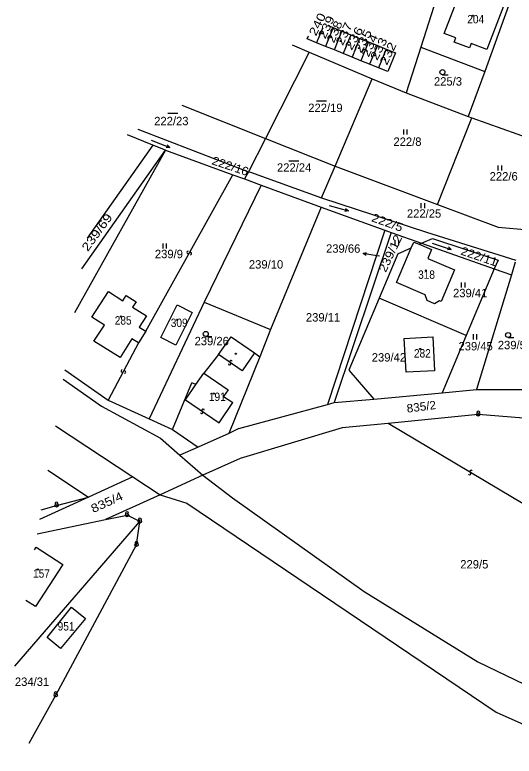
# Model space of a CAD drawing. Extents: x -680102 to -677253, y -1007548 to -1006096.
# Drawn here: x -680102.2 to -679953.4, y -1007313.8 to -1007092.8 of the extents above; entities that cross this region are included whole.
import ezdxf
from ezdxf.enums import TextEntityAlignment as Align

# ---------------------------------------------------------------- set-up
doc = ezdxf.new("R2010")
doc.units = 0
for name, color, linetype, lineweight in [('1', 7, 'Continuous', 25), ('16', 7, 'Continuous', 25), ('24', 7, 'Continuous', 25), ('25', 7, 'Continuous', 25), ('4', 7, 'Continuous', 25)]:
    doc.layers.add(name, color=color, linetype=linetype, lineweight=lineweight)
doc.layers.add('18', color=7, linetype='Continuous')
doc.layers.add('19', color=7, linetype='Continuous')

msp = doc.modelspace()

# ---------------------------------------------------------------- linework, layer by layer
at = {"layer": '1'}
for p, q in [((-679954.1, -1007087.39), (-679962.13, -1007109.73)), ((-680010.48, -1007096.84), (-680012.22, -1007101.17)), ((-680007.33, -1007096.64), (-680009.58, -1007102.24)), ((-680015, -1007100.04), (-680014.62, -1007099.1)), ((-680006.94, -1007103.31), (-680004.69, -1007097.71)), ((-680002.05, -1007098.79), (-680004.29, -1007104.38)), ((-679999.4, -1007099.86), (-680001.65, -1007105.45)), ((-679996.76, -1007100.93), (-679999.01, -1007106.52)), ((-680014.47, -1007103.93), (-680027.49, -1007129.66)), ((-679994.12, -1007102), (-679996.46, -1007107.56)), ((-679991.48, -1007103.07), (-679993.81, -1007108.63)), ((-679995.66, -1007111.97), (-679985.54, -1007116.09)), ((-680052.38, -1007119.74), (-680027.49, -1007129.66)), ((-679976.19, -1007149.36), (-679965.95, -1007123.53)), ((-679967.03, -1007123.14), (-679965.95, -1007123.53)), ((-679965.95, -1007123.53), (-679939.69, -1007132.98)), ((-680065.52, -1007126.92), (-680032.52, -1007139.6)), ((-680027.49, -1007129.66), (-680032.52, -1007139.6)), ((-680061.04, -1007131.67), (-680080.61, -1007159.45)), ((-680057.23, -1007133.22), (-680084.35, -1007181.65)), ((-680057.23, -1007133.22), (-680037.22, -1007140.53)), ((-680032.52, -1007139.6), (-680033.67, -1007141.76)), ((-680032.52, -1007139.6), (-680031.91, -1007139.77)), ((-680031.91, -1007139.77), (-680010.73, -1007147.42)), ((-680010.73, -1007147.42), (-679979.45, -1007157.58)), ((-680010.89, -1007150.15), (-679991.93, -1007157.07)), ((-679991.93, -1007157.07), (-680008.97, -1007208.97)), ((-679990.02, -1007157.74), (-680006.98, -1007208.43)), ((-679979.45, -1007157.58), (-679952.82, -1007166)), ((-679977.68, -1007159.47), (-679958.14, -1007165.97)), ((-679988.44, -1007172.65), (-679984.02, -1007162.31)), ((-679988.03, -1007164.1), (-679984.02, -1007162.31)), ((-679988.03, -1007164.1), (-679993.6, -1007177.35)), ((-679958.14, -1007165.97), (-679959.31, -1007168.57)), ((-679959.31, -1007168.57), (-679967.65, -1007188.43)), ((-679959.31, -1007168.57), (-679954.19, -1007170.32)), ((-680045.78, -1007178.51), (-680025.98, -1007186.66)), ((-679967.65, -1007188.43), (-679993.6, -1007177.35)), ((-680025.98, -1007186.66), (-680029.16, -1007194.76)), ((-680041.43, -1007194.05), (-680037.7, -1007188.79)), ((-679967.65, -1007188.43), (-679974.82, -1007205.5)), ((-680041.43, -1007194.05), (-680045.88, -1007199.68)), ((-680029.16, -1007194.76), (-680038.41, -1007217.67)), ((-680087.23, -1007198.68), (-680074.37, -1007207.67)), ((-680048.18, -1007203.06), (-680045.88, -1007199.68)), ((-680087.7, -1007201.45), (-680076.31, -1007209.52)), ((-680055.18, -1007216.43), (-680049.41, -1007202.57)), ((-680048.18, -1007203.06), (-680049.41, -1007202.57)), ((-679964.56, -1007204.56), (-679950.27, -1007204.57)), ((-680074.37, -1007207.67), (-680062.13, -1007213.23)), ((-680006.98, -1007208.43), (-679995.21, -1007207.36)), ((-680076.31, -1007209.52), (-680058.75, -1007219.05)), ((-679964.05, -1007211.96), (-679967.04, -1007212.27)), ((-679931.64, -1007214.53), (-679964.05, -1007211.96)), ((-680004.58, -1007216), (-680035.02, -1007225.06)), ((-680047.56, -1007221.68), (-680052.94, -1007224.14)), ((-680092.28, -1007228.56), (-680080.15, -1007236.6)), ((-680066.94, -1007230.55), (-680080.15, -1007236.6)), ((-680058.82, -1007235.88), (-680075.13, -1007243.3)), ((-680064.88, -1007243.83), (-680068.71, -1007241.97)), ((-680102.15, -1007287.01), (-680064.88, -1007243.83)), ((-680096.03, -1007269.2), (-680098.83, -1007267.38))]:
    msp.add_line(p, q, dxfattribs=at)
for points in [[(-679974.23, -1007080.64), (-679981.15, -1007102.52), (-679962.13, -1007109.73), (-679967.03, -1007123.14)], [(-680008.93, -1007095.99), (-680007.33, -1007096.64), (-680004.69, -1007097.71), (-680002.05, -1007098.79), (-679999.4, -1007099.86), (-679996.76, -1007100.93), (-679994.12, -1007102), (-679991.48, -1007103.07), (-679988.73, -1007104.19), (-679990.98, -1007109.74), (-679993.81, -1007108.63), (-679996.46, -1007107.56), (-679999.01, -1007106.52), (-680001.65, -1007105.45), (-680004.29, -1007104.38), (-680006.94, -1007103.31), (-680009.58, -1007102.24), (-680012.22, -1007101.17), (-680015, -1007100.04)], [(-680019.55, -1007101.8), (-680014.47, -1007103.93), (-679995.66, -1007111.97)], [(-679981.15, -1007102.52), (-679985.54, -1007116.09), (-679967.03, -1007123.14)], [(-680010.73, -1007147.42), (-680006.7, -1007137.95), (-679995.66, -1007111.97)], [(-680082.15, -1007168.6), (-680057.23, -1007133.22), (-680061.04, -1007131.67), (-680068.59, -1007128.6)], [(-680027.49, -1007129.66), (-680006.7, -1007137.95), (-679976.19, -1007149.36)], [(-680037.22, -1007140.53), (-680033.67, -1007141.76), (-680028.71, -1007143.64)], [(-680028.71, -1007143.64), (-680045.78, -1007178.51), (-680062.13, -1007213.23)], [(-680028.71, -1007143.64), (-680010.89, -1007150.15), (-680025.98, -1007186.66)], [(-679976.19, -1007149.36), (-679958.13, -1007156.11), (-679949.13, -1007156.98)], [(-679991.93, -1007157.07), (-679990.02, -1007157.74), (-679980.96, -1007160.94), (-679959.31, -1007168.57)], [(-679981.65, -1007161.25), (-679977.95, -1007162.8), (-679979.07, -1007165.44), (-679971.09, -1007168.82), (-679975.1, -1007178.3), (-679975.57, -1007178.14), (-679977.13, -1007179.02), (-679979.28, -1007178.03), (-679979.84, -1007176.32), (-679988.44, -1007172.65)], [(-679984.02, -1007162.31), (-679983.27, -1007160.57), (-679981.65, -1007161.25)], [(-679981.65, -1007161.25), (-679980.96, -1007160.94), (-679977.68, -1007159.47)], [(-679953.04, -1007166.53), (-679954.19, -1007170.32), (-679964.56, -1007204.56)], [(-679993.6, -1007177.35), (-680002.6, -1007198.77), (-679995.21, -1007207.36)], [(-680037.7, -1007188.79), (-680030.76, -1007193.64), (-680029.16, -1007194.76)], [(-679995.21, -1007207.36), (-679974.82, -1007205.5), (-679964.56, -1007204.56)], [(-680035.44, -1007216.12), (-680008.97, -1007208.97), (-680006.98, -1007208.43)], [(-679967.04, -1007212.27), (-679990.92, -1007214.64), (-680004.58, -1007216)], [(-680062.13, -1007213.23), (-680055.18, -1007216.43), (-680047.56, -1007221.68)], [(-680090.05, -1007215.38), (-680066.94, -1007230.55), (-680058.82, -1007235.88)], [(-680035.44, -1007216.12), (-680038.41, -1007217.67), (-680047.56, -1007221.68)], [(-680058.75, -1007219.05), (-680052.94, -1007224.14), (-680046.12, -1007230.11)], [(-680035.02, -1007225.06), (-680046.12, -1007230.11), (-680037.24, -1007236.8), (-679998.03, -1007264.71), (-679964.14, -1007285.74), (-679942.13, -1007296.31)], [(-680046.12, -1007230.11), (-680058.82, -1007235.88), (-680050.85, -1007238.38), (-679958.75, -1007300.67), (-679925.02, -1007315.68), (-679907.39, -1007320.2)], [(-680094.27, -1007240.39), (-680089.72, -1007239.08), (-680080.15, -1007236.6), (-680094.77, -1007243.29)], [(-680095.48, -1007247.51), (-680075.13, -1007243.3), (-680068.71, -1007241.97)], [(-680097.92, -1007309.98), (-680089.97, -1007295.64), (-680065.88, -1007250.79), (-680064.88, -1007243.83)], [(-680096.28, -1007252.27), (-680095.78, -1007251.5), (-680087.86, -1007256.65), (-680096.03, -1007269.2)]]:
    msp.add_lwpolyline(points, dxfattribs=at)
for points in [[(-680069, -1007176.54), (-680066.03, -1007178.42), (-680067.04, -1007180.02), (-680062.96, -1007182.59), (-680065.09, -1007185.97), (-680063.12, -1007187.17), (-680065.25, -1007190.62), (-680067.24, -1007189.38), (-680070.81, -1007195.03), (-680078.58, -1007190.11), (-680075.47, -1007185.31), (-680079.16, -1007182.92), (-680074.22, -1007175.3), (-680070.01, -1007178.14)], [(-680053.8, -1007179.31), (-680049.31, -1007181.55), (-680054.15, -1007191.28), (-680058.65, -1007189.05)], [(-679986.15, -1007189.3), (-679977.56, -1007188.87), (-679977.07, -1007198.92), (-679985.58, -1007199.36)], [(-680092.52, -1007278.42), (-680085.27, -1007269.45), (-680081.14, -1007272.75), (-680088.53, -1007281.71)]]:
    msp.add_lwpolyline(points, close=True, dxfattribs=at)
at = {"layer": '16'}
for p, q in [((-679995.44, -1007164.48), (-679998.394, -1007163.96)), ((-679993.5, -1007164.82), (-679995.44, -1007164.48))]:
    msp.add_line(p, q, dxfattribs=at)
msp.add_lwpolyline([(-679997.496, -1007164.625), (-679998.394, -1007163.96), (-679997.322, -1007163.641)], dxfattribs=at)
at = {"layer": '24'}
for centre, radius in [((-679964.05, -1007211.96), 0.5), ((-679964.05, -1007211.96), 0.022), ((-680089.72, -1007239.08), 0.5), ((-680089.72, -1007239.08), 0.022), ((-680068.71, -1007241.97), 0.5), ((-680068.71, -1007241.97), 0.022), ((-680064.88, -1007243.83), 0.5), ((-680064.88, -1007243.83), 0.022), ((-680065.88, -1007250.79), 0.5), ((-680065.88, -1007250.79), 0.022), ((-680089.97, -1007295.64), 0.5), ((-680089.97, -1007295.64), 0.022)]:
    msp.add_circle(centre, radius, dxfattribs=at)
for centre in [(-679964.051, -1007211.397), (-680089.721, -1007238.517), (-680068.711, -1007241.407), (-680064.881, -1007243.267), (-680065.881, -1007250.227), (-680089.971, -1007295.077)]:
    msp.add_arc(centre, 0.437, 328.35109, 209.97456, dxfattribs=at)
at = {"layer": '25'}
for p, q in [((-679974.73, -1007110.68), (-679972.98, -1007110.68)), ((-680012.29, -1007118.49), (-680009.29, -1007118.49)), ((-680056.53, -1007122.13), (-680053.53, -1007122.13)), ((-679986.257, -1007128.505), (-679986.257, -1007127.005)), ((-679985.223, -1007128.505), (-679985.223, -1007127.005)), ((-680061.573, -1007130.206), (-680055.987, -1007132.394)), ((-680020.48, -1007136.39), (-680017.48, -1007136.39)), ((-679958.107, -1007139.265), (-679958.107, -1007137.765)), ((-679957.073, -1007139.265), (-679957.073, -1007137.765)), ((-680008.513, -1007149.634), (-680002.747, -1007151.286)), ((-679981.047, -1007150.515), (-679981.047, -1007149.015)), ((-679980.013, -1007150.515), (-679980.013, -1007149.015)), ((-680057.947, -1007162.505), (-680057.947, -1007161.005)), ((-680056.913, -1007162.505), (-680056.913, -1007161.005)), ((-679988.787, -1007161.495), (-679988.787, -1007159.995)), ((-679987.753, -1007161.495), (-679987.753, -1007159.995)), ((-679977.781, -1007160.859), (-679972.099, -1007162.781)), ((-679969.027, -1007174.105), (-679969.027, -1007172.605)), ((-679967.993, -1007174.105), (-679967.993, -1007172.605)), ((-679965.477, -1007189.575), (-679965.477, -1007188.075)), ((-679964.443, -1007189.575), (-679964.443, -1007188.075)), ((-680045.24, -1007188.72), (-680043.49, -1007188.72)), ((-679955.17, -1007189.03), (-679953.42, -1007189.03))]:
    msp.add_line(p, q, dxfattribs=at)
for points in [[(-680056.736, -1007131.564), (-680055.987, -1007132.394), (-680057.101, -1007132.495)], [(-680003.57, -1007150.53), (-680002.747, -1007151.286), (-680003.846, -1007151.491)], [(-679972.886, -1007161.987), (-679972.099, -1007162.781), (-679973.206, -1007162.934)]]:
    msp.add_lwpolyline(points, dxfattribs=at)
for centre, radius in [((-679965.67, -1007093.11), 0.175), ((-680010.54, -1007098.38), 0.122), ((-680007.89, -1007099.549), 0.122), ((-680005.12, -1007100.66), 0.122), ((-680002.65, -1007101.829), 0.122), ((-679999.689, -1007102.76), 0.122), ((-679997.22, -1007103.62), 0.122), ((-679994.939, -1007104.98), 0.122), ((-679991.919, -1007106.15), 0.122), ((-679974.73, -1007109.93), 0.75), ((-679979.67, -1007169.04), 0.175), ((-680070.57, -1007182.75), 0.175), ((-680053.77, -1007183.76), 0.175), ((-680045.24, -1007187.97), 0.75), ((-679955.17, -1007188.28), 0.75), ((-679981.39, -1007192.43), 0.175), ((-680036.28, -1007193.85), 0.175), ((-680042.85, -1007205.75), 0.175), ((-680095.34, -1007258.18), 0.175)]:
    msp.add_circle(centre, radius, dxfattribs=at)
for centre, radius, start, end in [((-680050.49, -1007163.669), 0.367, 98.46662, 330.50904), ((-680049.85, -1007164.032), 0.368, 278.26413, 150.60557), ((-680038.154, -1007196.829), 0.368, 182.10019, 54.40841), ((-680037.724, -1007196.231), 0.369, 1.86264, 234.02644), ((-680070.133, -1007198.972), 0.368, 99.2326, 330.91533), ((-680069.487, -1007199.326), 0.368, 278.99441, 151.41561), ((-680046.471, -1007211.312), 0.369, 183.1123, 55.19834), ((-680046.051, -1007210.708), 0.368, 2.79028, 235.31659), ((-679966.581, -1007229.584), 0.367, 186.36185, 58.68914), ((-679966.197, -1007228.956), 0.368, 6.54634, 238.66072)]:
    msp.add_arc(centre, radius, start, end, dxfattribs=at)
at = {"layer": '4'}
for p, q in [((-680063.12, -1007187.17), (-680037.22, -1007140.53)), ((-680065.25, -1007190.62), (-680074.37, -1007207.67)), ((-680034.45, -1007199), (-680041.43, -1007194.05)), ((-680030.76, -1007193.64), (-680034.45, -1007199)), ((-680051.27, -1007207.59), (-680048.18, -1007203.06))]:
    msp.add_line(p, q, dxfattribs=at)
msp.add_lwpolyline([(-679969.24, -1007085.47), (-679956.58, -1007090.26), (-679961.46, -1007103.19), (-679966.21, -1007101.39), (-679966.71, -1007102.7), (-679971.2, -1007101), (-679970.71, -1007099.69), (-679974.17, -1007098.38)], close=True, dxfattribs=at)
for points in [[(-680045.88, -1007199.68), (-680038.57, -1007204.66), (-680039.93, -1007206.66), (-680037.18, -1007208.44)], [(-680051.27, -1007207.59), (-680041.25, -1007214.42), (-680037.18, -1007208.44)], [(-679896.91, -1007258.73), (-679937.6, -1007240.42), (-679939.65, -1007245.21), (-679941.86, -1007243.89), (-679990.92, -1007214.64)]]:
    msp.add_lwpolyline(points, dxfattribs=at)

# ---------------------------------------------------------------- texts
at = {"layer": '16'}
msp.add_text('239/66', height=2.5, dxfattribs=at).set_placement((-679999.19, -1007163.76), align=Align.RIGHT)
at = {"layer": '18'}
for s, p in [('225/3', (-679977.26, -1007113.93)), ('222/19', (-680014.72, -1007121.82)), ('222/8', (-679989.33, -1007131.9)), ('222/6', (-679960.66, -1007142.23)), ('239/9', (-680060.42, -1007165.38)), ('239/10', (-680032.4, -1007168.48)), ('239/41', (-679971.57, -1007177.02)), ('239/11', (-680015.42, -1007184.26)), ('239/26', (-680048.59, -1007191.34)), ('239/5', (-679958.23, -1007192.53)), ('239/42', (-679995.79, -1007196.2)), ('229/5', (-679969.41, -1007257.88))]:
    msp.add_text(s, height=2.5, dxfattribs=at).set_placement(p)
for s, p in [('222/23', (-680055.51, -1007125.75)), ('222/24', (-680018.929, -1007139.61)), ('222/25', (-679980.209, -1007153.32)), ('239/45', (-679964.84, -1007192.87)), ('234/31', (-680097.02, -1007292.88))]:
    msp.add_text(s, height=2.5, dxfattribs=at).set_placement(p, align=Align.CENTER)
for s, height, rotation, width, p in [('222/16', 2.5, 341.603, 1.1, (-680043.678, -1007137.334)), ('222/5', 2.5, 340.303, 1.15, (-679996.095, -1007154.31)), ('239/12', 2.5, 64.801, 1.15, (-679991.625, -1007169.794)), ('222/11', 2.5, 341.203, 1.1, (-679969.497, -1007164.246)), ('239/66', 0.1, 70.901, 1.1, (-679993.623, -1007164.566)), ('835/4', 2.5, 24.5, 1.2, (-680078.781, -1007241.366))]:
    msp.add_text(s, height=height, rotation=rotation, dxfattribs=dict(at, width=width)).set_placement(p)
for s, rotation, width, p in [('239/69', 54, 1.25, (-680076.664, -1007158.405)), ('835/2', 7.3, 1.05, (-679980.862, -1007210.882))]:
    msp.add_text(s, height=2.5, rotation=rotation, dxfattribs=dict(at, width=width)).set_placement(p, align=Align.CENTER)
at = {"layer": '18', "width": 0.9}
msp.add_text('951', height=2.5, dxfattribs=at).set_placement((-680086.87, -1007276.37), align=Align.CENTER)
at = {"layer": '19'}
for s, rotation, width, p in [('240', 63.901, 1.25, (-680012.421, -1007099.343)), ('239', 65.401, 1.25, (-680009.648, -1007100.205)), ('238', 66.701, 1.2, (-680007.074, -1007101.448)), ('237', 65.001, 1.25, (-680004.406, -1007102.185)), ('236', 60.1, 1.3, (-680001.793, -1007103.597)), ('235', 62.4, 1.3, (-679998.974, -1007104.461)), ('234', 65.501, 1.25, (-679996.709, -1007105.636)), ('233', 63.301, 1.25, (-679994.168, -1007106.622)), ('232', 65.001, 1.25, (-679991.276, -1007108.045))]:
    msp.add_text(s, height=2.5, rotation=rotation, dxfattribs=dict(at, width=width)).set_placement(p)
at = {"layer": '19', "width": 0.9}
for s, p in [('204', (-679967.33, -1007095.39)), ('285', (-680072.38, -1007185.18)), ('309', (-680055.68, -1007185.89)), ('282', (-679983.22, -1007194.99)), ('191', (-680044.33, -1007207.95)), ('157', (-680096.72, -1007260.62))]:
    msp.add_text(s, height=2.5, dxfattribs=at).set_placement(p)
msp.add_text('318', height=2.5, dxfattribs=at).set_placement((-679979.47, -1007171.53), align=Align.CENTER)

doc.saveas('drawing.dxf')
